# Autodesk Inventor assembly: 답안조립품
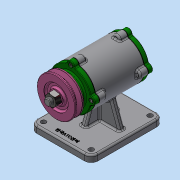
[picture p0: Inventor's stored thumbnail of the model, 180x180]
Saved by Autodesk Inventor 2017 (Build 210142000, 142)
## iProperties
Part Number: 답안조립품
Material: 일반
Document SubType Name: Assembly
Designer: MRC
Author: MRC
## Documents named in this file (12)
- C:\Users\MRC\Desktop\720716V1002\답안조립품.iam
- C:\Users\MRC\Desktop\720716V1002\본체.ipt
- C:\Users\MRC\Desktop\720716V1002\V-벨트풀리.ipt
- C:\Users\MRC\Desktop\720716V1002\개스킷.ipt
- C:\Users\MRC\Desktop\720716V1002\너트 M12 x 1.25.ipt
- C:\Users\MRC\Desktop\720716V1002\뒤커버.ipt
- C:\Users\MRC\Desktop\720716V1002\베어링 6204.ipt
- C:\Users\MRC\Desktop\720716V1002\볼트 M4 x 12.ipt
- C:\Users\MRC\Desktop\720716V1002\앞커버.ipt
- C:\Users\MRC\Desktop\720716V1002\오일 실.ipt
- C:\Users\MRC\Desktop\720716V1002\축.ipt
- C:\Users\MRC\Desktop\720716V1002\키 4 x 4.ipt
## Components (3 placed, 2 different names)
1. V-벨트풀리:1
2. 개스킷:1
3. 개스킷:2
